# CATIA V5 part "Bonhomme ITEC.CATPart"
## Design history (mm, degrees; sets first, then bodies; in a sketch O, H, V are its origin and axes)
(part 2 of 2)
    line L744 (7.9268, -60.4192) -> (7.969, -60.4279)
    line L745 (7.969, -60.4279) -> (8.0127, -60.4332)
    line L746 (8.0127, -60.4332) -> (8.0579, -60.4349)
    line L747 (8.0579, -60.4349) -> (8.0987, -60.4339)
    line L748 (8.0987, -60.4339) -> (8.1376, -60.4307)
    line L749 (8.1376, -60.4307) -> (8.1744, -60.4255)
    line L750 (8.1744, -60.4255) -> (8.2093, -60.4182)
    line L751 (8.2093, -60.4182) -> (8.2421, -60.4087)
    line L752 (8.2421, -60.4087) -> (8.2729, -60.3972)
    line L753 (8.2729, -60.3972) -> (8.3017, -60.3836)
    line L754 (8.3017, -60.3836) -> (8.3285, -60.3679)
    line L755 (8.3285, -60.3679) -> (8.3532, -60.3501)
    line L756 (8.3532, -60.3501) -> (8.376, -60.3302)
    line L757 (8.376, -60.3302) -> (8.3979, -60.308)
    line L758 (8.3979, -60.308) -> (8.4202, -60.283)
    line L759 (8.4202, -60.283) -> (8.4429, -60.2554)
    line L760 (8.4429, -60.2554) -> (8.466, -60.2251)
    line L761 (8.466, -60.2251) -> (8.4894, -60.1922)
    line L762 (8.4894, -60.1922) -> (8.5132, -60.1566)
    line L763 (8.5132, -60.1566) -> (8.5373, -60.1183)
    line L764 (8.5373, -60.1183) -> (8.5619, -60.0774)
    line L765 (8.5619, -60.0774) -> (8.5868, -60.0338)
    line L766 (8.5868, -60.0338) -> (8.612, -59.9875)
    line L767 (8.612, -59.9875) -> (8.6455, -59.9208)
    line L768 (8.6455, -59.9208) -> (8.6803, -59.8572)
    line L769 (8.6803, -59.8572) -> (8.7164, -59.7965)
    line L770 (8.7164, -59.7965) -> (8.7539, -59.7389)
    line L771 (8.7539, -59.7389) -> (8.7926, -59.6842)
    line L772 (8.7926, -59.6842) -> (8.8327, -59.6326)
    line L773 (8.8327, -59.6326) -> (8.8741, -59.5839)
    line L774 (8.8741, -59.5839) -> (8.9168, -59.5382)
    line L775 (8.9168, -59.5382) -> (8.9608, -59.4956)
    line L776 (8.9608, -59.4956) -> (9.0061, -59.4559)
    line L777 (9.0061, -59.4559) -> (9.0549, -59.4196)
    line L778 (9.0549, -59.4196) -> (9.1092, -59.3872)
    line L779 (9.1092, -59.3872) -> (9.1691, -59.3585)
    line L780 (9.1691, -59.3585) -> (9.2346, -59.3337)
    line L781 (9.2346, -59.3337) -> (9.3058, -59.3127)
    line L782 (9.3058, -59.3127) -> (9.3824, -59.2955)
    line L783 (9.3824, -59.2955) -> (9.4647, -59.2822)
    line L784 (9.4647, -59.2822) -> (9.5525, -59.2726)
    line L785 (9.5525, -59.2726) -> (9.646, -59.2669)
    line L786 (9.646, -59.2669) -> (9.745, -59.265)
    line L787 (9.745, -59.265) -> (9.8376, -59.2671)
    line L788 (9.8376, -59.2671) -> (9.9265, -59.2733)
    line L789 (9.9265, -59.2733) -> (10.0118, -59.2837)
    line L790 (10.0118, -59.2837) -> (10.0934, -59.2982)
    line L791 (10.0934, -59.2982) -> (10.1714, -59.3168)
    line L792 (10.1714, -59.3168) -> (10.2457, -59.3396)
    line L793 (10.2457, -59.3396) -> (10.3164, -59.3666)
    line L794 (10.3164, -59.3666) -> (10.3834, -59.3977)
    line L795 (10.3834, -59.3977) -> (10.4467, -59.4329)
    line L796 (10.4467, -59.4329) -> (10.5064, -59.4723)
    line L797 (10.5064, -59.4723) -> (10.5614, -59.5146)
    line L798 (10.5614, -59.5146) -> (10.6106, -59.5586)
    line L799 (10.6106, -59.5586) -> (10.654, -59.6043)
    line L800 (10.654, -59.6043) -> (10.6916, -59.6516)
    line L801 (10.6916, -59.6516) -> (10.7235, -59.7007)
    line L802 (10.7235, -59.7007) -> (10.7495, -59.7514)
    line L803 (10.7495, -59.7514) -> (10.7698, -59.8037)
    line L804 (10.7698, -59.8037) -> (10.7843, -59.8578)
    line L805 (10.7843, -59.8578) -> (10.7929, -59.9136)
    line L806 (10.7929, -59.9136) -> (10.7958, -59.9711)
    line L807 (10.7958, -59.9711) -> (10.7948, -60.0067)
    line L808 (10.7948, -60.0067) -> (10.7919, -60.0413)
    line L809 (10.7919, -60.0413) -> (10.787, -60.075)
    line L810 (10.787, -60.075) -> (10.7801, -60.1077)
    line L811 (10.7801, -60.1077) -> (10.7712, -60.1393)
    line L812 (10.7712, -60.1393) -> (10.7604, -60.1701)
    line L813 (10.7604, -60.1701) -> (10.7475, -60.1998)
    line L814 (10.7475, -60.1998) -> (10.7328, -60.2285)
    line L815 (10.7328, -60.2285) -> (10.716, -60.2562)
    line L816 (10.716, -60.2562) -> (10.6973, -60.283)
    line L817 (10.6973, -60.283) -> (10.6769, -60.3089)
    line L818 (10.6769, -60.3089) -> (10.6549, -60.3341)
    line L819 (10.6549, -60.3341) -> (10.6316, -60.3585)
    line L820 (10.6316, -60.3585) -> (10.6067, -60.3822)
    line L821 (10.6067, -60.3822) -> (10.5803, -60.4051)
    line L822 (10.5803, -60.4051) -> (10.5525, -60.4274)
    line L823 (10.5525, -60.4274) -> (10.5232, -60.4488)
    line L824 (10.5232, -60.4488) -> (10.4924, -60.4695)
    line L825 (10.4924, -60.4695) -> (10.4601, -60.4895)
    line L826 (10.4601, -60.4895) -> (10.4264, -60.5088)
    line L827 (10.4264, -60.5088) -> (10.3919, -60.5273)
    line L828 (10.3919, -60.5273) -> (10.3573, -60.5449)
    line L829 (10.3573, -60.5449) -> (10.3226, -60.5617)
    line L830 (10.3226, -60.5617) -> (10.2878, -60.5777)
    line L831 (10.2878, -60.5777) -> (10.253, -60.5929)
    line L832 (10.253, -60.5929) -> (10.218, -60.6073)
    line L833 (10.218, -60.6073) -> (10.183, -60.6208)
    line L834 (10.183, -60.6208) -> (10.1479, -60.6336)
    line L835 (10.1479, -60.6336) -> (10.1127, -60.6455)
    line L836 (10.1127, -60.6455) -> (10.0775, -60.6566)
    line L837 (10.0775, -60.6566) -> (10.0399, -60.6677)
    line L838 (10.0399, -60.6677) -> (9.9977, -60.6799)
    line L839 (9.9977, -60.6799) -> (9.9509, -60.693)
    line L840 (9.9509, -60.693) -> (9.8995, -60.7072)
    line L841 (9.8995, -60.7072) -> (9.8435, -60.7222)
    line L842 (9.8435, -60.7222) -> (9.7829, -60.7383)
    line L843 (9.7829, -60.7383) -> (9.7177, -60.7554)
    line L844 (9.7177, -60.7554) -> (9.6479, -60.7735)
    line L845 (9.6479, -60.7735) -> (9.5736, -60.7925)
    line L846 (9.5736, -60.7925) -> (9.4946, -60.8126)
    line L847 (9.4946, -60.8126) -> (9.3937, -60.8366)
    line L848 (9.3937, -60.8366) -> (9.2948, -60.8611)
    line L849 (9.2948, -60.8611) -> (9.1979, -60.8862)
    line L850 (9.1979, -60.8862) -> (9.1028, -60.9117)
    line L851 (9.1028, -60.9117) -> (9.0097, -60.9378)
    line L852 (9.0097, -60.9378) -> (8.9185, -60.9643)
    line L853 (8.9185, -60.9643) -> (8.8292, -60.9913)
    line L854 (8.8292, -60.9913) -> (8.7419, -61.0188)
    line L855 (8.7419, -61.0188) -> (8.6565, -61.0468)
    line L856 (8.6565, -61.0468) -> (8.573, -61.0753)
    line L857 (8.573, -61.0753) -> (8.4918, -61.1046)
    line L858 (8.4918, -61.1046) -> (8.4129, -61.1352)
    line L859 (8.4129, -61.1352) -> (8.3366, -61.167)
    line L860 (8.3366, -61.167) -> (8.2627, -61.2001)
    line L861 (8.2627, -61.2001) -> (8.1913, -61.2343)
    line L862 (8.1913, -61.2343) -> (8.1223, -61.2698)
    line L863 (8.1223, -61.2698) -> (8.0558, -61.3066)
    line L864 (8.0558, -61.3066) -> (7.9918, -61.3445)
    line L865 (7.9918, -61.3445) -> (7.9302, -61.3838)
    line L866 (7.9302, -61.3838) -> (7.8711, -61.4242)
    line L867 (7.8711, -61.4242) -> (7.8145, -61.4663)
    line L868 (7.8145, -61.4663) -> (7.7604, -61.5106)
    line L869 (7.7604, -61.5106) -> (7.7089, -61.5571)
    line L870 (7.7089, -61.5571) -> (7.6599, -61.6058)
    line L871 (7.6599, -61.6058) -> (7.6135, -61.6566)
    line L872 (7.6135, -61.6566) -> (7.5696, -61.7096)
    line L873 (7.5696, -61.7096) -> (7.5283, -61.7648)
    line L874 (7.5283, -61.7648) -> (7.4895, -61.8222)
    line L875 (7.4895, -61.8222) -> (7.4533, -61.8817)
    line L876 (7.4533, -61.8817) -> (7.4196, -61.9434)
    line L877 (7.4196, -61.9434) -> (7.3888, -62.0077)
    line L878 (7.3888, -62.0077) -> (7.3612, -62.0747)
    line L879 (7.3612, -62.0747) -> (7.3369, -62.1446)
    line L880 (7.3369, -62.1446) -> (7.3158, -62.2173)
    line L881 (7.3158, -62.2173) -> (7.298, -62.2929)
    line L882 (7.298, -62.2929) -> (7.2834, -62.3713)
    line L883 (7.2834, -62.3713) -> (7.272, -62.4525)
    line L884 (7.272, -62.4525) -> (7.2639, -62.5365)
    line L885 (7.2639, -62.5365) -> (7.259, -62.6234)
    line L886 (7.259, -62.6234) -> (7.2574, -62.7131)
    line L887 (7.2574, -62.7131) -> (7.2602, -62.8212)
    line L888 (7.2602, -62.8212) -> (7.2687, -62.927)
    line L889 (7.2687, -62.927) -> (7.2827, -63.0307)
    line L890 (7.2827, -63.0307) -> (7.3024, -63.1322)
    line L891 (7.3024, -63.1322) -> (7.3277, -63.2314)
    line L892 (7.3277, -63.2314) -> (7.3586, -63.3284)
    line L893 (7.3586, -63.3284) -> (7.3952, -63.4231)
    line L894 (7.3952, -63.4231) -> (7.4374, -63.5157)
    line L895 (7.4374, -63.5157) -> (7.4852, -63.6061)
    line L896 (7.4852, -63.6061) -> (7.5386, -63.6942)
    line L897 (7.5386, -63.6942) -> (7.5974, -63.7793)
    line L898 (7.5974, -63.7793) -> (7.6615, -63.8607)
    line L899 (7.6615, -63.8607) -> (7.7308, -63.9383)
    line L900 (7.7308, -63.9383) -> (7.8053, -64.0121)
    line L901 (7.8053, -64.0121) -> (7.885, -64.0821)
    line L902 (7.885, -64.0821) -> (7.9699, -64.1483)
    line L903 (7.9699, -64.1483) -> (8.06, -64.2108)
    line L904 (8.06, -64.2108) -> (8.1553, -64.2695)
    line L905 (8.1553, -64.2695) -> (8.2559, -64.3244)
    line L906 (8.2559, -64.3244) -> (8.3616, -64.3756)
    line L907 (8.3616, -64.3756) -> (8.472, -64.4224)
    line L908 (8.472, -64.4224) -> (8.5864, -64.4643)
    line L909 (8.5864, -64.4643) -> (8.7048, -64.5012)
    line L910 (8.7048, -64.5012) -> (8.8273, -64.5332)
    line L911 (8.8273, -64.5332) -> (8.9538, -64.5603)
    line L912 (8.9538, -64.5603) -> (9.0843, -64.5825)
    line L913 (9.0843, -64.5825) -> (9.2188, -64.5997)
    line L914 (9.2188, -64.5997) -> (9.3573, -64.612)
    line L915 (9.3573, -64.612) -> (9.4999, -64.6194)
    line L916 (9.4999, -64.6194) -> (9.6465, -64.6219)
    line L917 (9.6465, -64.6219) -> (9.8215, -64.6185)
    line L918 (9.8215, -64.6185) -> (9.9903, -64.6084)
    line L919 (9.9903, -64.6084) -> (10.1528, -64.5916)
    line L920 (10.1528, -64.5916) -> (10.3092, -64.568)
    line L921 (10.3092, -64.568) -> (10.4592, -64.5377)
    line L922 (10.4592, -64.5377) -> (10.6031, -64.5007)
    line L923 (10.6031, -64.5007) -> (10.7407, -64.4569)
    line L924 (10.7407, -64.4569) -> (10.872, -64.4065)
    line L925 (10.872, -64.4065) -> (10.9971, -64.3492)
    line L926 (10.9971, -64.3492) -> (11.116, -64.2853)
    line L927 (11.116, -64.2853) -> (11.1966, -64.2352)
    line L928 (11.1966, -64.2352) -> (11.274, -64.1819)
    line L929 (11.274, -64.1819) -> (11.3484, -64.1254)
    line L930 (11.3484, -64.1254) -> (11.4198, -64.0656)
    line L931 (11.4198, -64.0656) -> (11.488, -64.0026)
    line L932 (11.488, -64.0026) -> (11.5532, -63.9363)
    line L933 (11.5532, -63.9363) -> (11.6153, -63.8668)
    line L934 (11.6153, -63.8668) -> (11.6743, -63.794)
    line L935 (11.6743, -63.794) -> (11.7302, -63.718)
    line L936 (11.7302, -63.718) -> (11.783, -63.6388)
    line L937 (11.783, -63.6388) -> (11.8318, -63.5581)
    line L938 (11.8318, -63.5581) -> (11.8754, -63.4779)
    line L939 (11.8754, -63.4779) -> (11.9139, -63.3982)
    line L940 (11.9139, -63.3982) -> (11.9472, -63.3189)
    line L941 (11.9472, -63.3189) -> (11.9755, -63.2401)
    line L942 (11.9755, -63.2401) -> (11.9986, -63.1617)
    line L943 (11.9986, -63.1617) -> (12.0165, -63.0838)
    line L944 (12.0165, -63.0838) -> (12.0293, -63.0063)
    line L945 (12.0293, -63.0063) -> (12.037, -62.9292)
    line L946 (12.037, -62.9292) -> (12.0396, -62.8527)
    line L947 (12.0396, -62.8527) -> (12.0381, -62.809)
    line L948 (12.0381, -62.809) -> (12.0334, -62.7665)
    line L949 (12.0334, -62.7665) -> (12.0258, -62.7254)
    line L950 (12.0258, -62.7254) -> (12.015, -62.6855)
    line L951 (12.015, -62.6855) -> (12.0011, -62.6469)
    line L952 (12.0011, -62.6469) -> (11.9842, -62.6096)
    line L953 (11.9842, -62.6096) -> (11.9642, -62.5735)
    line L954 (11.9642, -62.5735) -> (11.9411, -62.5387)
    line L955 (11.9411, -62.5387) -> (11.9149, -62.5052)
    line L956 (11.9149, -62.5052) -> (11.8857, -62.473)
    line L957 (11.8857, -62.473) -> (11.854, -62.4429)
    line L958 (11.854, -62.4429) -> (11.8207, -62.4161)
    line L959 (11.8207, -62.4161) -> (11.7857, -62.3924)
    line L960 (11.7857, -62.3924) -> (11.7491, -62.3718)
    line L961 (11.7491, -62.3718) -> (11.7107, -62.3544)
    line L962 (11.7107, -62.3544) -> (11.6707, -62.3402)
    line L963 (11.6707, -62.3402) -> (11.6289, -62.3292)
    line L964 (11.6289, -62.3292) -> (11.5855, -62.3213)
    line L965 (11.5855, -62.3213) -> (11.5404, -62.3165)
    line L966 (11.5404, -62.3165) -> (11.4937, -62.3149)
    line L967 (11.4937, -62.3149) -> (11.4557, -62.3162)
    line L968 (11.4557, -62.3162) -> (11.4189, -62.3199)
    line L969 (11.4189, -62.3199) -> (11.3833, -62.326)
    line L970 (11.3833, -62.326) -> (11.3488, -62.3346)
    line L971 (11.3488, -62.3346) -> (11.3156, -62.3457)
    line L972 (11.3156, -62.3457) -> (11.2836, -62.3593)
    line L973 (11.2836, -62.3593) -> (11.2527, -62.3753)
    line L974 (11.2527, -62.3753) -> (11.2231, -62.3938)
    line L975 (11.2231, -62.3938) -> (11.1946, -62.4147)
    line L976 (11.1946, -62.4147) -> (11.1673, -62.4381)
    line L977 (11.1673, -62.4381) -> (11.141, -62.4639)
    line L978 (11.141, -62.4639) -> (11.1155, -62.4921)
    line L979 (11.1155, -62.4921) -> (11.0908, -62.5227)
    line L980 (11.0908, -62.5227) -> (11.0668, -62.5556)
    line L981 (11.0668, -62.5556) -> (11.0437, -62.591)
    line L982 (11.0437, -62.591) -> (11.0213, -62.6287)
    line L983 (11.0213, -62.6287) -> (10.9997, -62.6688)
    line L984 (10.9997, -62.6688) -> (10.9788, -62.7113)
    line L985 (10.9788, -62.7113) -> (10.9588, -62.7562)
    line L986 (10.9588, -62.7562) -> (10.9395, -62.8034)
    line L987 (10.9395, -62.8034) -> (10.9163, -62.86)
    line L988 (10.9163, -62.86) -> (10.8928, -62.9146)
    line L989 (10.8928, -62.9146) -> (10.8689, -62.9673)
    line L990 (10.8689, -62.9673) -> (10.8446, -63.0182)
    line L991 (10.8446, -63.0182) -> (10.8199, -63.0671)
    line L992 (10.8199, -63.0671) -> (10.7949, -63.1142)
    line L993 (10.7949, -63.1142) -> (10.7695, -63.1594)
    line L994 (10.7695, -63.1594) -> (10.7438, -63.2027)
    line L995 (10.7438, -63.2027) -> (10.7176, -63.2442)
    line L996 (10.7176, -63.2442) -> (10.6912, -63.2837)
    line L997 (10.6912, -63.2837) -> (10.6634, -63.3216)
    line L998 (10.6634, -63.3216) -> (10.6334, -63.3581)
    line L999 (10.6334, -63.3581) -> (10.6013, -63.3934)
  Pad3: profile Sketch14, direction (-1, 0, 0), up to the existing solid (limit type 2), offset 1
  Sketch15 on yz-plane, origin (0, 0, 0), H (0, 1, 0), V (0, 0, 1)
    line L1 (-8.6678, -64.5193) -> (-7.0792, -64.5193)
    line L2 (-7.0792, -64.5193) -> (-7.0144, -64.5183)
    line L3 (-7.0144, -64.5183) -> (-6.9528, -64.5152)
    line L4 (-6.9528, -64.5152) -> (-6.8945, -64.5102)
    line L5 (-6.8945, -64.5102) -> (-6.8395, -64.5032)
    line L6 (-6.8395, -64.5032) -> (-6.7878, -64.4941)
    line L7 (-6.7878, -64.4941) -> (-6.7393, -64.4831)
    line L8 (-6.7393, -64.4831) -> (-6.6942, -64.47)
    line L9 (-6.6942, -64.47) -> (-6.6523, -64.4549)
    line L10 (-6.6523, -64.4549) -> (-6.6137, -64.4378)
    line L11 (-6.6137, -64.4378) -> (-6.5784, -64.4187)
    line L12 (-6.5784, -64.4187) -> (-6.5459, -64.3977)
    line L13 (-6.5459, -64.3977) -> (-6.5158, -64.3752)
    line L14 (-6.5158, -64.3752) -> (-6.488, -64.351)
    line L15 (-6.488, -64.351) -> (-6.4625, -64.3251)
    line L16 (-6.4625, -64.3251) -> (-6.4394, -64.2976)
    line L17 (-6.4394, -64.2976) -> (-6.4186, -64.2684)
    line L18 (-6.4186, -64.2684) -> (-6.4001, -64.2377)
    line L19 (-6.4001, -64.2377) -> (-6.384, -64.2052)
    line L20 (-6.384, -64.2052) -> (-6.3703, -64.1712)
    line L21 (-6.3703, -64.1712) -> (-6.3588, -64.1355)
    line L22 (-6.3588, -64.1355) -> (-6.3491, -64.0978)
    line L23 (-6.3491, -64.0978) -> (-6.3403, -64.058)
    line L24 (-6.3403, -64.058) -> (-6.3326, -64.0161)
    line L25 (-6.3326, -64.0161) -> (-6.326, -63.9719)
    line L26 (-6.326, -63.9719) -> (-6.3203, -63.9256)
    line L27 (-6.3203, -63.9256) -> (-6.3157, -63.8771)
    line L28 (-6.3157, -63.8771) -> (-6.3121, -63.8264)
    line L29 (-6.3121, -63.8264) -> (-6.3096, -63.7736)
    line L30 (-6.3096, -63.7736) -> (-6.308, -63.7185)
    line L31 (-6.308, -63.7185) -> (-6.3075, -63.6614)
    line L32 (-6.3075, -63.6614) -> (-6.3075, -59.2486)
    line L33 (-6.3075, -59.2486) -> (-6.3093, -59.172)
    line L34 (-6.3093, -59.172) -> (-6.3146, -59.0997)
    line L35 (-6.3146, -59.0997) -> (-6.3234, -59.0317)
    line L36 (-6.3234, -59.0317) -> (-6.3358, -58.9681)
    line L37 (-6.3358, -58.9681) -> (-6.3516, -58.9089)
    line L38 (-6.3516, -58.9089) -> (-6.3711, -58.854)
    line L39 (-6.3711, -58.854) -> (-6.394, -58.8035)
    line L40 (-6.394, -58.8035) -> (-6.4205, -58.7573)
    line L41 (-6.4205, -58.7573) -> (-6.4505, -58.7155)
    line L42 (-6.4505, -58.7155) -> (-6.484, -58.678)
    line L43 (-6.484, -58.678) -> (-6.5215, -58.6445)
    line L44 (-6.5215, -58.6445) -> (-6.5633, -58.6145)
    line L45 (-6.5633, -58.6145) -> (-6.6095, -58.588)
    line L46 (-6.6095, -58.588) -> (-6.66, -58.565)
    line L47 (-6.66, -58.565) -> (-6.7149, -58.5456)
    line L48 (-6.7149, -58.5456) -> (-6.7742, -58.5297)
    line L49 (-6.7742, -58.5297) -> (-6.8377, -58.5174)
    line L50 (-6.8377, -58.5174) -> (-6.9057, -58.5086)
    line L51 (-6.9057, -58.5086) -> (-6.978, -58.5033)
    line L52 (-6.978, -58.5033) -> (-7.0546, -58.5015)
    line L53 (-7.0546, -58.5015) -> (-8.6432, -58.5015)
    line L54 (-8.6432, -58.5015) -> (-8.7654, -58.5027)
    line L55 (-8.7654, -58.5027) -> (-8.8841, -58.5061)
    line L56 (-8.8841, -58.5061) -> (-8.9992, -58.5118)
    line L57 (-8.9992, -58.5118) -> (-9.1108, -58.5199)
    line L58 (-9.1108, -58.5199) -> (-9.2189, -58.5302)
    line L59 (-9.2189, -58.5302) -> (-9.3234, -58.5429)
    line L60 (-9.3234, -58.5429) -> (-9.4245, -58.5578)
    line L61 (-9.4245, -58.5578) -> (-9.522, -58.5751)
    line L62 (-9.522, -58.5751) -> (-9.6159, -58.5946)
    line L63 (-9.6159, -58.5946) -> (-9.7063, -58.6164)
    line L64 (-9.7063, -58.6164) -> (-9.7942, -58.6414)
    line L65 (-9.7942, -58.6414) -> (-9.8804, -58.6705)
    line L66 (-9.8804, -58.6705) -> (-9.965, -58.7035)
    line L67 (-9.965, -58.7035) -> (-10.0479, -58.7406)
    line L68 (-10.0479, -58.7406) -> (-10.1292, -58.7817)
    line L69 (-10.1292, -58.7817) -> (-10.2088, -58.8268)
    line L70 (-10.2088, -58.8268) -> (-10.2868, -58.8759)
    line L71 (-10.2868, -58.8759) -> (-10.3631, -58.9291)
    line L72 (-10.3631, -58.9291) -> (-10.4378, -58.9863)
    line L73 (-10.4378, -58.9863) -> (-10.5109, -59.0475)
    line L74 (-10.5109, -59.0475) -> (-10.6895, -59.2167)
    line L75 (-10.6895, -59.2167) -> (-10.8493, -59.4028)
    line L76 (-10.8493, -59.4028) -> (-10.9903, -59.6056)
    line L77 (-10.9903, -59.6056) -> (-11.1125, -59.8251)
    line L78 (-11.1125, -59.8251) -> (-11.2159, -60.0613)
    line L79 (-11.2159, -60.0613) -> (-11.3005, -60.3144)
    line L80 (-11.3005, -60.3144) -> (-11.3663, -60.5841)
    line L81 (-11.3663, -60.5841) -> (-11.4133, -60.8707)
    line L82 (-11.4133, -60.8707) -> (-11.4415, -61.174)
    line L83 (-11.4415, -61.174) -> (-11.4509, -61.494)
    line L84 (-11.4509, -61.494) -> (-11.45, -61.6014)
    line L85 (-11.45, -61.6014) -> (-11.4472, -61.7069)
    line L86 (-11.4472, -61.7069) -> (-11.4424, -61.8106)
    line L87 (-11.4424, -61.8106) -> (-11.4358, -61.9123)
    line L88 (-11.4358, -61.9123) -> (-11.4273, -62.0122)
    line L89 (-11.4273, -62.0122) -> (-11.4169, -62.1102)
    line L90 (-11.4169, -62.1102) -> (-11.4047, -62.2063)
    line L91 (-11.4047, -62.2063) -> (-11.3905, -62.3005)
    line L92 (-11.3905, -62.3005) -> (-11.3744, -62.3928)
    line L93 (-11.3744, -62.3928) -> (-11.3565, -62.4832)
    line L94 (-11.3565, -62.4832) -> (-11.3366, -62.5718)
    line L95 (-11.3366, -62.5718) -> (-11.3147, -62.6587)
    line L96 (-11.3147, -62.6587) -> (-11.2906, -62.7438)
    line L97 (-11.2906, -62.7438) -> (-11.2646, -62.8271)
    line L98 (-11.2646, -62.8271) -> (-11.2364, -62.9086)
    line L99 (-11.2364, -62.9086) -> (-11.2063, -62.9884)
    line L100 (-11.2063, -62.9884) -> (-11.174, -63.0664)
    line L101 (-11.174, -63.0664) -> (-11.1398, -63.1426)
    line L102 (-11.1398, -63.1426) -> (-11.1034, -63.2171)
    line L103 (-11.1034, -63.2171) -> (-11.0651, -63.2899)
    line L104 (-11.0651, -63.2899) -> (-11.0245, -63.3609)
    line L105 (-11.0245, -63.3609) -> (-10.9818, -63.4305)
    line L106 (-10.9818, -63.4305) -> (-10.9369, -63.4985)
    line L107 (-10.9369, -63.4985) -> (-10.8897, -63.565)
    line L108 (-10.8897, -63.565) -> (-10.8403, -63.63)
    line L109 (-10.8403, -63.63) -> (-10.7887, -63.6935)
    line L110 (-10.7887, -63.6935) -> (-10.7349, -63.7555)
    line L111 (-10.7349, -63.7555) -> (-10.6789, -63.8159)
    line L112 (-10.6789, -63.8159) -> (-10.6206, -63.8749)
    line L113 (-10.6206, -63.8749) -> (-10.5602, -63.9323)
    line L114 (-10.5602, -63.9323) -> (-10.5113, -63.9749)
    line L115 (-10.5113, -63.9749) -> (-10.4615, -64.0158)
    line L116 (-10.4615, -64.0158) -> (-10.4108, -64.055)
    line L117 (-10.4108, -64.055) -> (-10.3592, -64.0925)
    line L118 (-10.3592, -64.0925) -> (-10.3067, -64.1283)
    line L119 (-10.3067, -64.1283) -> (-10.2533, -64.1623)
    line L120 (-10.2533, -64.1623) -> (-10.199, -64.1946)
    line L121 (-10.199, -64.1946) -> (-10.1438, -64.2252)
    line L122 (-10.1438, -64.2252) -> (-10.0876, -64.254)
    line L123 (-10.0876, -64.254) -> (-10.0306, -64.2812)
    line L124 (-10.0306, -64.2812) -> (-9.9727, -64.3067)
    line L125 (-9.9727, -64.3067) -> (-9.914, -64.3306)
    line L126 (-9.914, -64.3306) -> (-9.8544, -64.353)
    line L127 (-9.8544, -64.353) -> (-9.7939, -64.3738)
    line L128 (-9.7939, -64.3738) -> (-9.7325, -64.393)
    line L129 (-9.7325, -64.393) -> (-9.6703, -64.4107)
    line L130 (-9.6703, -64.4107) -> (-9.6072, -64.4269)
    line L131 (-9.6072, -64.4269) -> (-9.5433, -64.4414)
    line L132 (-9.5433, -64.4414) -> (-9.4785, -64.4544)
    line L133 (-9.4785, -64.4544) -> (-9.4129, -64.4659)
    line L134 (-9.4129, -64.4659) -> (-9.3459, -64.476)
    line L135 (-9.3459, -64.476) -> (-9.2773, -64.4851)
    line L136 (-9.2773, -64.4851) -> (-9.207, -64.4931)
    line L137 (-9.207, -64.4931) -> (-9.135, -64.5001)
    line L138 (-9.135, -64.5001) -> (-9.0614, -64.5059)
    line L139 (-9.0614, -64.5059) -> (-8.986, -64.5107)
    line L140 (-8.986, -64.5107) -> (-8.909, -64.5145)
    line L141 (-8.909, -64.5145) -> (-8.8303, -64.5171)
    line L142 (-8.8303, -64.5171) -> (-8.7499, -64.5187)
    line L143 (-8.7499, -64.5187) -> (-8.6678, -64.5193)
    line L144 (-7.439, -63.5505) -> (-7.439, -59.4661)
    line L145 (-7.439, -59.4661) -> (-8.2436, -59.4661)
    line L146 (-8.2436, -59.4661) -> (-8.3536, -59.4674)
    line L147 (-8.3536, -59.4674) -> (-8.4603, -59.471)
    line L148 (-8.4603, -59.471) -> (-8.5638, -59.477)
    line L149 (-8.5638, -59.477) -> (-8.6639, -59.4855)
    line L150 (-8.6639, -59.4855) -> (-8.7608, -59.4964)
    line L151 (-8.7608, -59.4964) -> (-8.8544, -59.5097)
    line L152 (-8.8544, -59.5097) -> (-8.9447, -59.5255)
    line L153 (-8.9447, -59.5255) -> (-9.0317, -59.5436)
    line L154 (-9.0317, -59.5436) -> (-9.1155, -59.5642)
    line L155 (-9.1155, -59.5642) -> (-9.1959, -59.5872)
    line L156 (-9.1959, -59.5872) -> (-9.2735, -59.6147)
    line L157 (-9.2735, -59.6147) -> (-9.3486, -59.6486)
    line L158 (-9.3486, -59.6486) -> (-9.4211, -59.6889)
    line L159 (-9.4211, -59.6889) -> (-9.4912, -59.7357)
    line L160 (-9.4912, -59.7357) -> (-9.5587, -59.7889)
    line L161 (-9.5587, -59.7889) -> (-9.6237, -59.8486)
    line L162 (-9.6237, -59.8486) -> (-9.6863, -59.9147)
    line L163 (-9.6863, -59.9147) -> (-9.7463, -59.9872)
    line L164 (-9.7463, -59.9872) -> (-9.8038, -60.0662)
    line L165 (-9.8038, -60.0662) -> (-9.8589, -60.1517)
    line L166 (-9.8589, -60.1517) -> (-9.91, -60.2448)
    line L167 (-9.91, -60.2448) -> (-9.9557, -60.3469)
    line L168 (-9.9557, -60.3469) -> (-9.996, -60.4579)
    line L169 (-9.996, -60.4579) -> (-10.0309, -60.5779)
    line L170 (-10.0309, -60.5779) -> (-10.0605, -60.7069)
    line L171 (-10.0605, -60.7069) -> (-10.0847, -60.8447)
    line L172 (-10.0847, -60.8447) -> (-10.1035, -60.9916)
    line L173 (-10.1035, -60.9916) -> (-10.117, -61.1473)
    line L174 (-10.117, -61.1473) -> (-10.125, -61.3121)
    line L175 (-10.125, -61.3121) -> (-10.1277, -61.4858)
    line L176 (-10.1277, -61.4858) -> (-10.1216, -61.7312)
    line L177 (-10.1216, -61.7312) -> (-10.1033, -61.9616)
    line L178 (-10.1033, -61.9616) -> (-10.0727, -62.1771)
    line L179 (-10.0727, -62.1771) -> (-10.0299, -62.3777)
    line L180 (-10.0299, -62.3777) -> (-9.9748, -62.5633)
    line L181 (-9.9748, -62.5633) -> (-9.9076, -62.734)
    line L182 (-9.9076, -62.734) -> (-9.828, -62.8897)
    line L183 (-9.828, -62.8897) -> (-9.7363, -63.0305)
    line L184 (-9.7363, -63.0305) -> (-9.6323, -63.1564)
    line L185 (-9.6323, -63.1564) -> (-9.5161, -63.2673)
    line L186 (-9.5161, -63.2673) -> (-9.4885, -63.2905)
    line L187 (-9.4885, -63.2905) -> (-9.4599, -63.3128)
    line L188 (-9.4599, -63.3128) -> (-9.4304, -63.3339)
    line L189 (-9.4304, -63.3339) -> (-9.3999, -63.354)
    line L190 (-9.3999, -63.354) -> (-9.3683, -63.373)
    line L191 (-9.3683, -63.373) -> (-9.3358, -63.3909)
    line L192 (-9.3358, -63.3909) -> (-9.3023, -63.4078)
    line L193 (-9.3023, -63.4078) -> (-9.2678, -63.4236)
    line L194 (-9.2678, -63.4236) -> (-9.2324, -63.4383)
    line L195 (-9.2324, -63.4383) -> (-9.1959, -63.452)
    line L196 (-9.1959, -63.452) -> (-9.1591, -63.4646)
    line L197 (-9.1591, -63.4646) -> (-9.1225, -63.4763)
    line L198 (-9.1225, -63.4763) -> (-9.0862, -63.487)
    line L199 (-9.0862, -63.487) -> (-9.0501, -63.4966)
    line L200 (-9.0501, -63.4966) -> (-9.0143, -63.5054)
    line L201 (-9.0143, -63.5054) -> (-8.9787, -63.5131)
    line L202 (-8.9787, -63.5131) -> (-8.9434, -63.5198)
    line L203 (-8.9434, -63.5198) -> (-8.9083, -63.5255)
    line L204 (-8.9083, -63.5255) -> (-8.8734, -63.5303)
    line L205 (-8.8734, -63.5303) -> (-8.8388, -63.5341)
    line L206 (-8.8388, -63.5341) -> (-8.803, -63.5372)
    line L207 (-8.803, -63.5372) -> (-8.7646, -63.54)
    line L208 (-8.7646, -63.54) -> (-8.7235, -63.5425)
    line L209 (-8.7235, -63.5425) -> (-8.6799, -63.5446)
    line L210 (-8.6799, -63.5446) -> (-8.6336, -63.5464)
    line L211 (-8.6336, -63.5464) -> (-8.5846, -63.5479)
    line L212 (-8.5846, -63.5479) -> (-8.5331, -63.549)
    line L213 (-8.5331, -63.549) -> (-8.4789, -63.5498)
    line L214 (-8.4789, -63.5498) -> (-8.4221, -63.5503)
    line L215 (-8.4221, -63.5503) -> (-8.3626, -63.5505)
    line L216 (-8.3626, -63.5505) -> (-7.439, -63.5505)
  Pad4: profile Sketch15, direction (-1, 0, 0), up to the existing solid (limit type 2), offset 1
  Sketch16 on yz-plane, origin (0, 0, 0), H (0, 1, 0), V (0, 0, 1)
    line L1 (8.5103, -61.2978) -> (8.5103, -58.1722)
    line L2 (8.5103, -58.1722) -> (9.5863, -58.1722)
    line L3 (9.5863, -58.1722) -> (9.5863, -57.7418)
    line L4 (9.5863, -57.7418) -> (6.9577, -57.7418)
    line L5 (6.9577, -57.7418) -> (6.9577, -58.1722)
    line L6 (6.9577, -58.1722) -> (8.0389, -58.1722)
    line L7 (8.0389, -58.1722) -> (8.0389, -61.2978)
    line L8 (8.0389, -61.2978) -> (8.5103, -61.2978)
    line L9 (6.4095, -60.3191) -> (6.5068, -59.5198)
    line L10 (6.5068, -59.5198) -> (6.4095, -58.7255)
    line L11 (6.4095, -58.7255) -> (6.2968, -58.4027)
    line L12 (6.2968, -58.4027) -> (6.1482, -58.1363)
    line L13 (6.1482, -58.1363) -> (5.728, -57.7725)
    line L14 (5.728, -57.7725) -> (5.4718, -57.6803)
    line L15 (5.4718, -57.6803) -> (5.19, -57.6444)
    line L16 (5.19, -57.6444) -> (4.6417, -57.7725)
    line L17 (4.6417, -57.7725) -> (4.2267, -58.1312)
    line L18 (4.2267, -58.1312) -> (3.9654, -58.7204)
    line L19 (3.9654, -58.7204) -> (3.8731, -59.5198)
    line L20 (3.8731, -59.5198) -> (3.9654, -60.3191)
    line L21 (3.9654, -60.3191) -> (4.2318, -60.9083)
    line L22 (4.2318, -60.9083) -> (4.6469, -61.2721)
    line L23 (4.6469, -61.2721) -> (5.19, -61.3951)
    line L24 (5.19, -61.3951) -> (5.728, -61.2721)
    line L25 (5.728, -61.2721) -> (6.1482, -60.9083)
    line L26 (6.1482, -60.9083) -> (6.4095, -60.3191)
    line L27 (6.0149, -59.5198) -> (5.9534, -58.9049)
    line L28 (5.9534, -58.9049) -> (5.7844, -58.4489)
    line L29 (5.7844, -58.4489) -> (5.523, -58.167)
    line L30 (5.523, -58.167) -> (5.19, -58.0697)
    line L31 (5.19, -58.0697) -> (4.8518, -58.167)
    line L32 (4.8518, -58.167) -> (4.5905, -58.4437)
    line L33 (4.5905, -58.4437) -> (4.4214, -58.8998)
    line L34 (4.4214, -58.8998) -> (4.365, -59.5198)
    line L35 (4.365, -59.5198) -> (4.4214, -60.1449)
    line L36 (4.4214, -60.1449) -> (4.5905, -60.5958)
    line L37 (4.5905, -60.5958) -> (4.8518, -60.8725)
    line L38 (4.8518, -60.8725) -> (5.19, -60.9647)
    line L39 (5.19, -60.9647) -> (5.523, -60.8725)
    line L40 (5.523, -60.8725) -> (5.7844, -60.5958)
    line L41 (5.7844, -60.5958) -> (5.9534, -60.1397)
    line L42 (5.9534, -60.1397) -> (6.0149, -59.5198)
    line L43 (2.8484, -61.0723) -> (3.0431, -60.8212)
    line L44 (3.0431, -60.8212) -> (3.1302, -61.2978)
    line L45 (3.1302, -61.2978) -> (3.3864, -61.2978)
    line L46 (3.3864, -61.2978) -> (3.3864, -59.3763)
    line L47 (3.3864, -59.3763) -> (2.09, -59.3763)
    line L48 (2.09, -59.3763) -> (2.09, -59.8118)
    line L49 (2.09, -59.8118) -> (2.8893, -59.8118)
    line L50 (2.8893, -59.8118) -> (2.8893, -59.8426)
    line L51 (2.8893, -59.8426) -> (2.8279, -60.314)
    line L52 (2.8279, -60.314) -> (2.6639, -60.6624)
    line L53 (2.6639, -60.6624) -> (2.4128, -60.8827)
    line L54 (2.4128, -60.8827) -> (2.1003, -60.9545)
    line L55 (2.1003, -60.9545) -> (1.7518, -60.8622)
    line L56 (1.7518, -60.8622) -> (1.4803, -60.5855)
    line L57 (1.4803, -60.5855) -> (1.3061, -60.1295)
    line L58 (1.3061, -60.1295) -> (1.2446, -59.5044)
    line L59 (1.2446, -59.5044) -> (1.3009, -58.8844)
    line L60 (1.3009, -58.8844) -> (1.4751, -58.4284)
    line L61 (1.4751, -58.4284) -> (1.7518, -58.1517)
    line L62 (1.7518, -58.1517) -> (2.1259, -58.0543)
    line L63 (2.1259, -58.0543) -> (2.3821, -58.1055)
    line L64 (2.3821, -58.1055) -> (2.5922, -58.249)
    line L65 (2.5922, -58.249) -> (2.7459, -58.4898)
    line L66 (2.7459, -58.4898) -> (2.833, -58.8126)
    line L67 (2.833, -58.8126) -> (3.3403, -58.8126)
    line L68 (3.3403, -58.8126) -> (3.207, -58.3208)
    line L69 (3.207, -58.3208) -> (2.956, -57.9518)
    line L70 (2.956, -57.9518) -> (2.6024, -57.7264)
    line L71 (2.6024, -57.7264) -> (2.1566, -57.6444)
    line L72 (2.1566, -57.6444) -> (1.5725, -57.7725)
    line L73 (1.5725, -57.7725) -> (1.1318, -58.1465)
    line L74 (1.1318, -58.1465) -> (0.85, -58.7358)
    line L75 (0.85, -58.7358) -> (0.7527, -59.5198)
    line L76 (0.7527, -59.5198) -> (0.85, -60.3088)
    line L77 (0.85, -60.3088) -> (1.1318, -60.8981)
    line L78 (1.1318, -60.8981) -> (1.5469, -61.2721)
    line L79 (1.5469, -61.2721) -> (2.0695, -61.3951)
    line L80 (2.0695, -61.3951) -> (2.3616, -61.3541)
    line L81 (2.3616, -61.3541) -> (2.6229, -61.2516)
    line L82 (2.6229, -61.2516) -> (2.8484, -61.0723)
    line L83 (-0.4002, -60.355) -> (-0.3746, -60.8161)
    line L84 (-0.3746, -60.8161) -> (-0.3438, -61.1184)
    line L85 (-0.3438, -61.1184) -> (-0.2824, -61.2978)
    line L86 (-0.2824, -61.2978) -> (0.2556, -61.2978)
    line L87 (0.2556, -61.2978) -> (0.2556, -61.2004)
    line L88 (0.2556, -61.2004) -> (0.1378, -61.0569)
    line L89 (0.1378, -61.0569) -> (0.0968, -60.7905)
    line L90 (0.0968, -60.7905) -> (0.0609, -60.2166)
    line L91 (0.0609, -60.2166) -> (-0.0262, -59.7913)
    line L92 (-0.0262, -59.7913) -> (-0.144, -59.6581)
    line L93 (-0.144, -59.6581) -> (-0.3285, -59.5607)
    line L94 (-0.3285, -59.5607) -> (-0.1235, -59.4326)
    line L95 (-0.1235, -59.4326) -> (0.0199, -59.2533)
    line L96 (0.0199, -59.2533) -> (0.1122, -59.0279)
    line L97 (0.1122, -59.0279) -> (0.1429, -58.7563)
    line L98 (0.1429, -58.7563) -> (0.0712, -58.3259)
    line L99 (0.0712, -58.3259) -> (-0.1338, -58.0031)
    line L100 (-0.1338, -58.0031) -> (-0.4719, -57.8084)
    line L101 (-0.4719, -57.8084) -> (-0.9331, -57.7418)
    line L102 (-0.9331, -57.7418) -> (-2.1218, -57.7418)
    line L103 (-2.1218, -57.7418) -> (-2.1218, -61.2978)
    line L104 (-2.1218, -61.2978) -> (-1.6453, -61.2978)
    line L105 (-1.6453, -61.2978) -> (-1.6453, -59.7964)
    line L106 (-1.6453, -59.7964) -> (-1.1586, -59.7964)
    line L107 (-1.1586, -59.7964) -> (-0.7999, -59.8118)
    line L108 (-0.7999, -59.8118) -> (-0.5744, -59.8835)
    line L109 (-0.5744, -59.8835) -> (-0.4514, -60.0526)
    line L110 (-0.4514, -60.0526) -> (-0.4002, -60.355)
    line L111 (-2.9161, -60.5906) -> (-2.8392, -59.945)
    line L112 (-2.8392, -59.945) -> (-2.8392, -57.7418)
    line L113 (-2.8392, -57.7418) -> (-3.3157, -57.7418)
    line L114 (-3.3157, -57.7418) -> (-3.3157, -59.9707)
    line L115 (-3.3157, -59.9707) -> (-3.3618, -60.4062)
    line L116 (-3.3618, -60.4062) -> (-3.5002, -60.7187)
    line L117 (-3.5002, -60.7187) -> (-3.7359, -60.9032)
    line L118 (-3.7359, -60.9032) -> (-4.0638, -60.9647)
    line L119 (-4.0638, -60.9647) -> (-4.402, -60.9032)
    line L120 (-4.402, -60.9032) -> (-4.6377, -60.7187)
    line L121 (-4.6377, -60.7187) -> (-4.776, -60.4113)
    line L122 (-4.776, -60.4113) -> (-4.817, -59.9707)
    line L123 (-4.817, -59.9707) -> (-4.817, -57.7418)
    line L124 (-4.817, -57.7418) -> (-5.2884, -57.7418)
    line L125 (-5.2884, -57.7418) -> (-5.2884, -59.945)
    line L126 (-5.2884, -59.945) -> (-5.2167, -60.5855)
    line L127 (-5.2167, -60.5855) -> (-4.9912, -61.0416)
    line L128 (-4.9912, -61.0416) -> (-4.6121, -61.3029)
    line L129 (-4.6121, -61.3029) -> (-4.0638, -61.3951)
    line L130 (-4.0638, -61.3951) -> (-3.5207, -61.3029)
    line L131 (-3.5207, -61.3029) -> (-3.1415, -61.0416)
    line L132 (-3.1415, -61.0416) -> (-2.9161, -60.5906)
    line L133 (-6.9127, -61.2978) -> (-6.9127, -58.1722)
    line L134 (-6.9127, -58.1722) -> (-5.8367, -58.1722)
    line L135 (-5.8367, -58.1722) -> (-5.8367, -57.7418)
    line L136 (-5.8367, -57.7418) -> (-8.4653, -57.7418)
    line L137 (-8.4653, -57.7418) -> (-8.4653, -58.1722)
    line L138 (-8.4653, -58.1722) -> (-7.3841, -58.1722)
    line L139 (-7.3841, -58.1722) -> (-7.3841, -61.2978)
    line L140 (-7.3841, -61.2978) -> (-6.9127, -61.2978)
    line L141 (-1.6453, -59.3609) -> (-1.0971, -59.3609)
    line L142 (-1.0971, -59.3609) -> (-0.7743, -59.3353)
    line L143 (-0.7743, -59.3353) -> (-0.5386, -59.2431)
    line L144 (-0.5386, -59.2431) -> (-0.4002, -59.0637)
    line L145 (-0.4002, -59.0637) -> (-0.349, -58.7665)
    line L146 (-0.349, -58.7665) -> (-0.3951, -58.4847)
    line L147 (-0.3951, -58.4847) -> (-0.5334, -58.3054)
    line L148 (-0.5334, -58.3054) -> (-0.7538, -58.208)
    line L149 (-0.7538, -58.208) -> (-1.0663, -58.1773)
    line L150 (-1.0663, -58.1773) -> (-1.6453, -58.1773)
    line L151 (-1.6453, -58.1773) -> (-1.6453, -59.3609)
    line L152 (10.6611, -65.4127) -> (10.5022, -65.6177)
    line L153 (10.5022, -65.6177) -> (10.2614, -65.7458)
    line L154 (10.2614, -65.7458) -> (9.9489, -65.7868)
    line L155 (9.9489, -65.7868) -> (9.6004, -65.7304)
    line L156 (9.6004, -65.7304) -> (9.334, -65.5664)
    line L157 (9.334, -65.5664) -> (9.1649, -65.3)
    line L158 (9.1649, -65.3) -> (9.1085, -64.9464)
    line L159 (9.1085, -64.9464) -> (8.6423, -64.9464)
    line L160 (8.6423, -64.9464) -> (8.7447, -65.4896)
    line L161 (8.7447, -65.4896) -> (9.0009, -65.8892)
    line L162 (9.0009, -65.8892) -> (9.3955, -66.1301)
    line L163 (9.3955, -66.1301) -> (9.9284, -66.2172)
    line L164 (9.9284, -66.2172) -> (10.4561, -66.1352)
    line L165 (10.4561, -66.1352) -> (10.8507, -65.9097)
    line L166 (10.8507, -65.9097) -> (11.1017, -65.5562)
    line L167 (11.1017, -65.5562) -> (11.194, -65.0899)
    line L168 (11.194, -65.0899) -> (11.1171, -64.6697)
    line L169 (11.1171, -64.6697) -> (10.9019, -64.3982)
    line L170 (10.9019, -64.3982) -> (10.5535, -64.2188)
    line L171 (10.5535, -64.2188) -> (10.0872, -64.0856)
    line L172 (10.0872, -64.0856) -> (9.6875, -63.9883)
    line L173 (9.6875, -63.9883) -> (9.4262, -63.8755)
    line L174 (9.4262, -63.8755) -> (9.2776, -63.7116)
    line L175 (9.2776, -63.7116) -> (9.2315, -63.4554)
    line L176 (9.2315, -63.4554) -> (9.2776, -63.2248)
    line L177 (9.2776, -63.2248) -> (9.4108, -63.0506)
    line L178 (9.4108, -63.0506) -> (9.6158, -62.9327)
    line L179 (9.6158, -62.9327) -> (9.8976, -62.8917)
    line L180 (9.8976, -62.8917) -> (10.1846, -62.943)
    line L181 (10.1846, -62.943) -> (10.41, -63.0813)
    line L182 (10.41, -63.0813) -> (10.5586, -63.3119)
    line L183 (10.5586, -63.3119) -> (10.6303, -63.6245)
    line L184 (10.6303, -63.6245) -> (11.0966, -63.6245)
    line L185 (11.0966, -63.6245) -> (11.0966, -63.6142)
    line L186 (11.0966, -63.6142) -> (11.0146, -63.1326)
    line L187 (11.0146, -63.1326) -> (10.7738, -62.7739)
    line L188 (10.7738, -62.7739) -> (10.3946, -62.5484)
    line L189 (10.3946, -62.5484) -> (9.8822, -62.4716)
    line L190 (9.8822, -62.4716) -> (9.4211, -62.5484)
    line L191 (9.4211, -62.5484) -> (9.0624, -62.7636)
    line L192 (9.0624, -62.7636) -> (8.8318, -63.0967)
    line L193 (8.8318, -63.0967) -> (8.7499, -63.5271)
    line L194 (8.7499, -63.5271) -> (8.8165, -63.9114)
    line L195 (8.8165, -63.9114) -> (9.0112, -64.1727)
    line L196 (9.0112, -64.1727) -> (9.3186, -64.3469)
    line L197 (9.3186, -64.3469) -> (9.7388, -64.4802)
    line L198 (9.7388, -64.4802) -> (10.1538, -64.598)
    line L199 (10.1538, -64.598) -> (10.4664, -64.7107)
    line L200 (10.4664, -64.7107) -> (10.656, -64.8747)
    line L201 (10.656, -64.8747) -> (10.7226, -65.1411)
    line L202 (10.7226, -65.1411) -> (10.6611, -65.4127)
    line L203 (6.2289, -64.4853) -> (7.8173, -64.4853)
    line L204 (7.8173, -64.4853) -> (7.8173, -64.06)
    line L205 (7.8173, -64.06) -> (6.2289, -64.06)
    line L206 (6.2289, -64.06) -> (6.2289, -62.9942)
    line L207 (6.2289, -62.9942) -> (7.971, -62.9942)
    line L208 (7.971, -62.9942) -> (7.971, -62.5638)
    line L209 (7.971, -62.5638) -> (5.7575, -62.5638)
    line L210 (5.7575, -62.5638) -> (5.7575, -66.1198)
    line L211 (5.7575, -66.1198) -> (8.012, -66.1198)
    line L212 (8.012, -66.1198) -> (8.012, -65.6894)
    line L213 (8.012, -65.6894) -> (6.2289, -65.6894)
    line L214 (6.2289, -65.6894) -> (6.2289, -64.4853)
    line L215 (4.2664, -66.0737) -> (4.4919, -65.8943)
    line L216 (4.4919, -65.8943) -> (4.6866, -65.6433)
    line L217 (4.6866, -65.6433) -> (4.7737, -66.1198)
    line L218 (4.7737, -66.1198) -> (5.0299, -66.1198)
    line L219 (5.0299, -66.1198) -> (5.0299, -64.1983)
    line L220 (5.0299, -64.1983) -> (3.7335, -64.1983)
    line L221 (3.7335, -64.1983) -> (3.7335, -64.6339)
    line L222 (3.7335, -64.6339) -> (4.5329, -64.6339)
    line L223 (4.5329, -64.6339) -> (4.5329, -64.6646)
    line L224 (4.5329, -64.6646) -> (4.4714, -65.136)
    line L225 (4.4714, -65.136) -> (4.3074, -65.4844)
    line L226 (4.3074, -65.4844) -> (4.0563, -65.7048)
    line L227 (4.0563, -65.7048) -> (3.7438, -65.7765)
    line L228 (3.7438, -65.7765) -> (3.3954, -65.6843)
    line L229 (3.3954, -65.6843) -> (3.1238, -65.4076)
    line L230 (3.1238, -65.4076) -> (2.9496, -64.9516)
    line L231 (2.9496, -64.9516) -> (2.8881, -64.3264)
    line L232 (2.8881, -64.3264) -> (2.9445, -63.7064)
    line L233 (2.9445, -63.7064) -> (3.1187, -63.2504)
    line L234 (3.1187, -63.2504) -> (3.3954, -62.9737)
    line L235 (3.3954, -62.9737) -> (3.7694, -62.8764)
    line L236 (3.7694, -62.8764) -> (4.0256, -62.9276)
    line L237 (4.0256, -62.9276) -> (4.2357, -63.0711)
    line L238 (4.2357, -63.0711) -> (4.3894, -63.3119)
    line L239 (4.3894, -63.3119) -> (4.4765, -63.6347)
    line L240 (4.4765, -63.6347) -> (4.9838, -63.6347)
    line L241 (4.9838, -63.6347) -> (4.8506, -63.1428)
    line L242 (4.8506, -63.1428) -> (4.5995, -62.7739)
    line L243 (4.5995, -62.7739) -> (4.2459, -62.5484)
    line L244 (4.2459, -62.5484) -> (3.8002, -62.4664)
    line L245 (3.8002, -62.4664) -> (3.216, -62.5945)
    line L246 (3.216, -62.5945) -> (2.7754, -62.9686)
    line L247 (2.7754, -62.9686) -> (2.4936, -63.5579)
    line L248 (2.4936, -63.5579) -> (2.3962, -64.3418)
    line L249 (2.3962, -64.3418) -> (2.4936, -65.1309)
    line L250 (2.4936, -65.1309) -> (2.7754, -65.7201)
    line L251 (2.7754, -65.7201) -> (3.1904, -66.0942)
    line L252 (3.1904, -66.0942) -> (3.713, -66.2172)
    line L253 (3.713, -66.2172) -> (4.0051, -66.1762)
    line L254 (4.0051, -66.1762) -> (4.2664, -66.0737)
    line L255 (1.2023, -66.0942) -> (1.6225, -65.7304)
    line L256 (1.6225, -65.7304) -> (1.8838, -65.1411)
    line L257 (1.8838, -65.1411) -> (1.9812, -64.3418)
    line L258 (1.9812, -64.3418) -> (1.8838, -63.5476)
    line L259 (1.8838, -63.5476) -> (1.7711, -63.2248)
    line L260 (1.7711, -63.2248) -> (1.6225, -62.9584)
    line L261 (1.6225, -62.9584) -> (1.2023, -62.5945)
    line L262 (1.2023, -62.5945) -> (0.9461, -62.5023)
    line L263 (0.9461, -62.5023) -> (0.6643, -62.4664)
    line L264 (0.6643, -62.4664) -> (0.1161, -62.5945)
    line L265 (0.1161, -62.5945) -> (-0.299, -62.9532)
    line L266 (-0.299, -62.9532) -> (-0.5603, -63.5425)
    line L267 (-0.5603, -63.5425) -> (-0.6525, -64.3418)
    line L268 (-0.6525, -64.3418) -> (-0.5603, -65.1411)
    line L269 (-0.5603, -65.1411) -> (-0.2939, -65.7304)
    line L270 (-0.2939, -65.7304) -> (0.1212, -66.0942)
    line L271 (0.1212, -66.0942) -> (0.6643, -66.2172)
    line L272 (0.6643, -66.2172) -> (1.2023, -66.0942)
    line L273 (1.4893, -64.3418) -> (1.4278, -63.7269)
    line L274 (1.4278, -63.7269) -> (1.2587, -63.2709)
    line L275 (1.2587, -63.2709) -> (0.9974, -62.9891)
    line L276 (0.9974, -62.9891) -> (0.6643, -62.8917)
    line L277 (0.6643, -62.8917) -> (0.3261, -62.9891)
    line L278 (0.3261, -62.9891) -> (0.0648, -63.2658)
    line L279 (0.0648, -63.2658) -> (-0.1043, -63.7218)
    line L280 (-0.1043, -63.7218) -> (-0.1606, -64.3418)
    line L281 (-0.1606, -64.3418) -> (-0.1043, -64.9669)
    line L282 (-0.1043, -64.9669) -> (0.0648, -65.4178)
    line L283 (0.0648, -65.4178) -> (0.3261, -65.6945)
    line L284 (0.3261, -65.6945) -> (0.6643, -65.7868)
    line L285 (0.6643, -65.7868) -> (0.9974, -65.6945)
    line L286 (0.9974, -65.6945) -> (1.2587, -65.4178)
    line L287 (1.2587, -65.4178) -> (1.4278, -64.9618)
    line L288 (1.4278, -64.9618) -> (1.4893, -64.3418)
    line L289 (-2.4203, -65.6996) -> (-3.071, -62.5638)
    line L290 (-3.071, -62.5638) -> (-3.7013, -62.5638)
    line L291 (-3.7013, -62.5638) -> (-3.7013, -66.1198)
    line L292 (-3.7013, -66.1198) -> (-3.3067, -66.1198)
    line L293 (-3.3067, -66.1198) -> (-3.3067, -62.8917)
    line L294 (-3.3067, -62.8917) -> (-2.6406, -66.1198)
    line L295 (-2.6406, -66.1198) -> (-2.2, -66.1198)
    line L296 (-2.2, -66.1198) -> (-1.539, -62.8917)
    line L297 (-1.539, -62.8917) -> (-1.539, -66.1198)
    line L298 (-1.539, -66.1198) -> (-1.1393, -66.1198)
    line L299 (-1.1393, -66.1198) -> (-1.1393, -62.5638)
    line L300 (-1.1393, -62.5638) -> (-1.7644, -62.5638)
    line L301 (-1.7644, -62.5638) -> (-2.4203, -65.6996)
    line L302 (-5.2692, -65.6894) -> (-5.2692, -62.9942)
    line L303 (-5.2692, -62.9942) -> (-4.6133, -62.9942)
    line L304 (-4.6133, -62.9942) -> (-4.6133, -62.5638)
    line L305 (-4.6133, -62.5638) -> (-6.3964, -62.5638)
    line L306 (-6.3964, -62.5638) -> (-6.3964, -62.9942)
    line L307 (-6.3964, -62.9942) -> (-5.7406, -62.9942)
    line L308 (-5.7406, -62.9942) -> (-5.7406, -65.6894)
    line L309 (-5.7406, -65.6894) -> (-6.3964, -65.6894)
    line L310 (-6.3964, -65.6894) -> (-6.3964, -66.1198)
    line L311 (-6.3964, -66.1198) -> (-4.6133, -66.1198)
    line L312 (-4.6133, -66.1198) -> (-4.6133, -65.6894)
    line L313 (-4.6133, -65.6894) -> (-5.2692, -65.6894)
    line L314 (-9.6296, -66.1198) -> (-7.3444, -66.1198)
    line L315 (-7.3444, -66.1198) -> (-7.3444, -65.6894)
    line L316 (-7.3444, -65.6894) -> (-9.1582, -65.6894)
    line L317 (-9.1582, -65.6894) -> (-9.1582, -62.5638)
    line L318 (-9.1582, -62.5638) -> (-9.6296, -62.5638)
    line L319 (-9.6296, -62.5638) -> (-9.6296, -66.1198)
  Pad5: profile Sketch16, direction (1, 0, 0), up to the existing solid (limit type 2), offset 0.5
  Point1: type Center, Curve edge [face of Fillet2 | face of Shaft2 from Sketch6.L3]
Body2 "Porte-clés"
  Solid1: linked copy from another document
  Scaling1: Reference {point type Center, Curve edge [face of Solid1 | face of Solid1]}, Ratio 0.5, ToTransfor Solid1
  Body3 "Anneau"
    Sketch17 on zx-plane, origin (0, 0, 0), H (-1, 0, 0), V (0, 0, 1)
      circle A1 centre (0, -22.9396) radius 0.75
      point P1 (0, -22.9396)
      reference projected line E1 (0, -27.9437) -> (0, -22.9437) from Sketch18.A1
      radius A1 = 0.75
      coincidence: P1 V, P1 E1
    Sketch18 on yz-plane, origin (0, 0, 0), H (0, 1, 0), V (0, 0, 1)
      circle A1 centre (0, -25.4437) radius 2.5
      point P1 (0, -25.4437)
      radius A1 = 2.5
      coincidence: P1 V
    Rib2: profile Sketch17, centre curve Sketch18
  Add1: tool Body3
Body4 "Presse-papier"
  Solid2: linked copy from another document
  Body5 "Pied"
    Sketch19 on yz-plane, origin (0, 0, 0), H (0, 1, 0), V (0, 0, 1)
      line L1 (0, -102.025) -> (-10, -102.025)
      line L2 (-10, -102.025) -> (-25, -107.025)
      line L3 (-25, -107.025) -> (-25, -112.025)
      line L4 (-25, -112.025) -> (0, -112.025)
      point P5 (0, -112.025)
      axis line L5 (0, -102.025) -> (0, -112.025)
      reference projected point E1 (0, -102.025) from edge
      reference projected point E2 (0, -102.025) from edge
      length L3 = 5
      distance L3 L5 = 25
      length L1 = 10
      distance L1 L4 = 10
      horizontal: L1 H, L4 H
      perpendicularity: L3 L1
      vertical: L5 V
      coincidence: L1 E1, L5 E2, P5 L5
    Shaft6: profile Sketch19, axis Sketch19.L5, angle 360
    Fillet9: radius 3, on edge [face of Shaft6 from Sketch19.L1 | face of Shaft6 from Sketch19.L2]; edge [face of Shaft6 from Sketch19.L2 | face of Shaft6 from Sketch19.L3]
    Fillet10: radius 0.5, on edge [face of Shaft6 from Sketch19.L3 | face of Shaft6 from Sketch19.L4]
  Add2: tool Body5
  Point2: type Center, Curve edge [face of Solid2 | face of Solid2]
  Sketch20 on zx-plane, origin (0, 0, 0), H (-1, 0, 0), V (0, 0, 1)
    circle A1 centre (0, -24.1057) radius 0.75
    point P1 (0, -24.1057)
    radius A1 = 0.75
    coincidence: P1 V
